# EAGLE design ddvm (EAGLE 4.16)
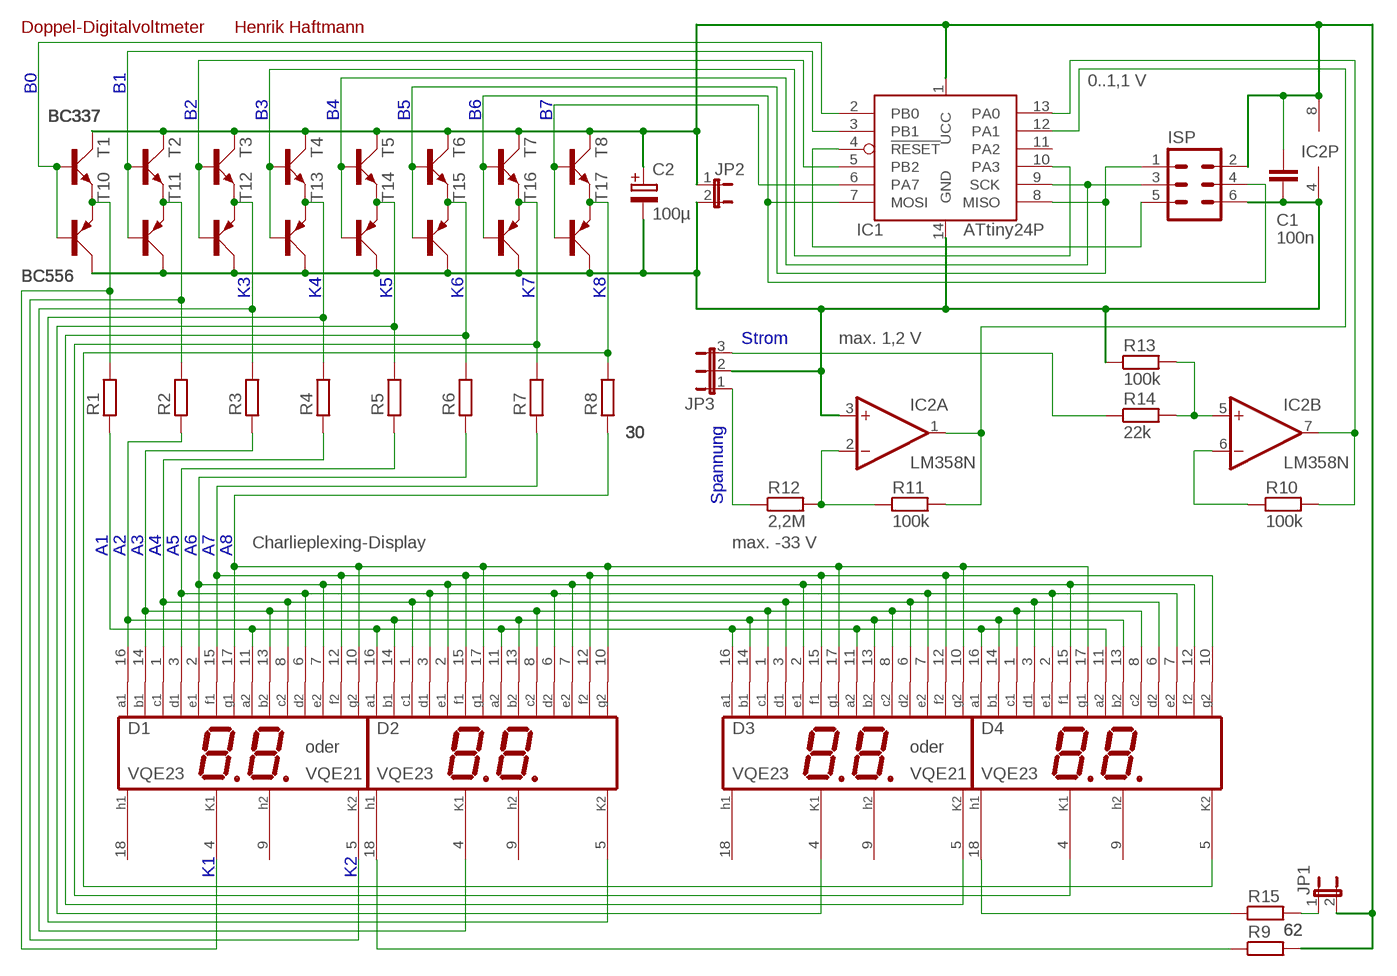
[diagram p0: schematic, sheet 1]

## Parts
C1  100n  C1  [C050-050X075]
C2  100µ  E1-2  [E1-2]
D1  VQE23  [VQE]
D2  VQE23  [VQE]
D3  VQE23  [VQE]
D4  VQE23  [VQE]
IC1  ATtiny24P  ATTINY24P  [DIL14]
IC2  LM358N  [DIL08]
ISP  MA03-2  [MA03-2]
JP1  JP1E  [JP1]
JP2  JP1E  [JP1]
JP3  JP2E  [JP2]
R1  30  R  [0207/2V]
R2  30  R  [0207/2V]
R3  30  R  [0207/2V]
R4  30  R  [0207/2V]
R5  30  R  [0207/2V]
R6  30  R  [0207/2V]
R7  30  R  [0207/2V]
R8  30  R  [0207/2V]
R9  62  R  [0207/2V]
R10  100k  R  [0207/2V]
R11  100k  R  [0207/2V]
R12  2,2M  R  [0207/2V]
R13  100k  R  [0207/2V]
R14  22k  R  [0207/2V]
R15  62  R  [0207/2V]
T1  BC337  NPN  [SOT54A]
T2  BC337  NPN  [SOT54A]
T3  BC337  NPN  [SOT54A]
T4  BC337  NPN  [SOT54A]
T5  BC337  NPN  [SOT54A]
T6  BC337  NPN  [SOT54A]
T7  BC337  NPN  [SOT54A]
T8  BC337  NPN  [SOT54A]
T10  BC556  PNP  [SOT54A]
T11  BC556  PNP  [SOT54A]
T12  BC556  PNP  [SOT54A]
T13  BC556  PNP  [SOT54A]
T14  BC556  PNP  [SOT54A]
T15  BC556  PNP  [SOT54A]
T16  BC556  PNP  [SOT54A]
T17  BC556  PNP  [SOT54A]

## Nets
5P: C1.1 C2.+ IC1.1(UCC) IC2.8(P:V+) ISP.2 JP1.2 JP2.1 R9.2 T1.C T2.C T3.C T4.C T5.C T6.C T7.C T8.C
A1: D1.11(A2) D2.11(A2) D2.16(A1) D3.11(A2) D3.16(A1) D4.11(A2) D4.16(A1) R1.1
A2: D1.16(A1) D2.13(B2) D2.14(B1) D3.13(B2) D3.14(B1) D4.13(B2) D4.14(B1) R2.1
A3: D1.13(B2) D1.14(B1) D2.8(C2) D3.1(C1) D3.8(C2) D4.1(C1) D4.8(C2) R3.1
A4: D1.1(C1) D1.8(C2) D2.1(C1) D3.3(D1) D3.6(D2) D4.3(D1) D4.6(D2) R4.1
A5: D1.3(D1) D1.6(D2) D2.3(D1) D2.6(D2) D3.7(E2) D4.2(E1) D4.7(E2) R5.1
A6: D1.2(E1) D1.7(E2) D2.2(E1) D2.7(E2) D3.2(E1) D4.12(F2) D4.15(F1) R6.1
A7: D1.12(F2) D1.15(F1) D2.12(F2) D2.15(F1) D3.12(F2) D3.15(F1) D4.10(G2) R7.1
A8: D1.10(G2) D1.17(G1) D2.10(G2) D2.17(G1) D3.10(G2) D3.17(G1) D4.17(G1) R8.1
B0: IC1.2(PB0) T1.B T10.B
B1: IC1.3(PB1) T2.B T11.B
B2: IC1.5(PB2) T3.B T12.B
B3: IC1.10(PA3) T4.B T13.B
B4: IC1.9(SCK) ISP.3 T5.B T14.B
B5: IC1.8(MISO) ISP.1 T6.B T15.B
B6: IC1.7(MOSI) ISP.4 T7.B T16.B
B7: IC1.6(PA7) T8.B T17.B
GND: C1.2 C2.- IC1.14(GND) IC2.3(A:+IN) IC2.4(P:V-) ISP.6 JP2.2 JP3.2 R13.1 T10.C T11.C T12.C T13.C T14.C T15.C T16.C T17.C
K1: D1.4(GK1) R1.2 T1.E T10.E
K2: D1.5(GK2) R2.2 T2.E T11.E
K3: D2.4(GK1) R3.2 T3.E T12.E
K4: D2.5(GK2) R4.2 T4.E T13.E
K5: D3.4(GK1) R5.2 T5.E T14.E
K6: D3.5(GK2) R6.2 T6.E T15.E
K7: D4.4(GK1) R7.2 T7.E T16.E
K8: D4.5(GK2) R8.2 T8.E T17.E
N$9: D2.18(H1) R9.1
N$18: D4.18(H1) R15.1
N$27: JP1.1 R15.2
N$30: JP3.1 R12.1
N$31: IC1.4(!RESET) ISP.5
N$32: JP3.3 R14.1
N$34: IC1.13(PA0) IC2.7(B:OUT) R10.2
N$35: IC1.12(PA1) IC2.1(A:OUT) R11.2
N$36: IC2.2(A:-IN) R11.1 R12.2
N$37: IC2.5(B:+IN) R13.2 R14.2
N$38: IC2.6(B:-IN) R10.1
Unconnected: D1.9(H2) D1.18(H1) D2.9(H2) D3.9(H2) D3.18(H1) D4.9(H2) IC1.11(PA2)

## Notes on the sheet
- Doppel-Digitalvoltmeter | Henrik Haftmann
- 0..1,1 V
- Strom | max. 1,2 V
- Spannung
- Charlieplexing-Display | max. -33 V
- oder | oder
- VQE21 | VQE21

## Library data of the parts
C1 = UZD1:C: Kondensator
C2 = galep:E: Elektrolytkondensator, gepolt
D1-D4 = UZD1:VQE*: LED-Anzeige 2 7-Segment-Ziffern 8.8.
IC1 = UZD1:ATTINY*4: 8-bit-Mikrocontroller Typmax. TaktFlashRAMEEPROM ATtiny2420 MHz2 kByte128 Byte128 Byte ATtiny24V10 MHz ATtiny4420 MHz4 kByte256 Byte256 Byte ATtiny44V10 MHz ATtiny84V10 MHz8 kByte512 Byte512 Byte
IC2 = linear:LM358: OP AMP also LM158; LM258; LM2904 Source: http://cache.national.com/ds/LM/LM158.pdf
ISP = con-lstb:MA03-2: PIN HEADER
JP1 JP2 = jumper:JP1E: JUMPER
JP3 = jumper:JP2E: JUMPER
R1-R15 = UZD1:R: Widerstand
T1-T8 = UZD1:NPN: npn-Trabsistor
T10-T17 = UZD1:PNP: pnp-Transistor

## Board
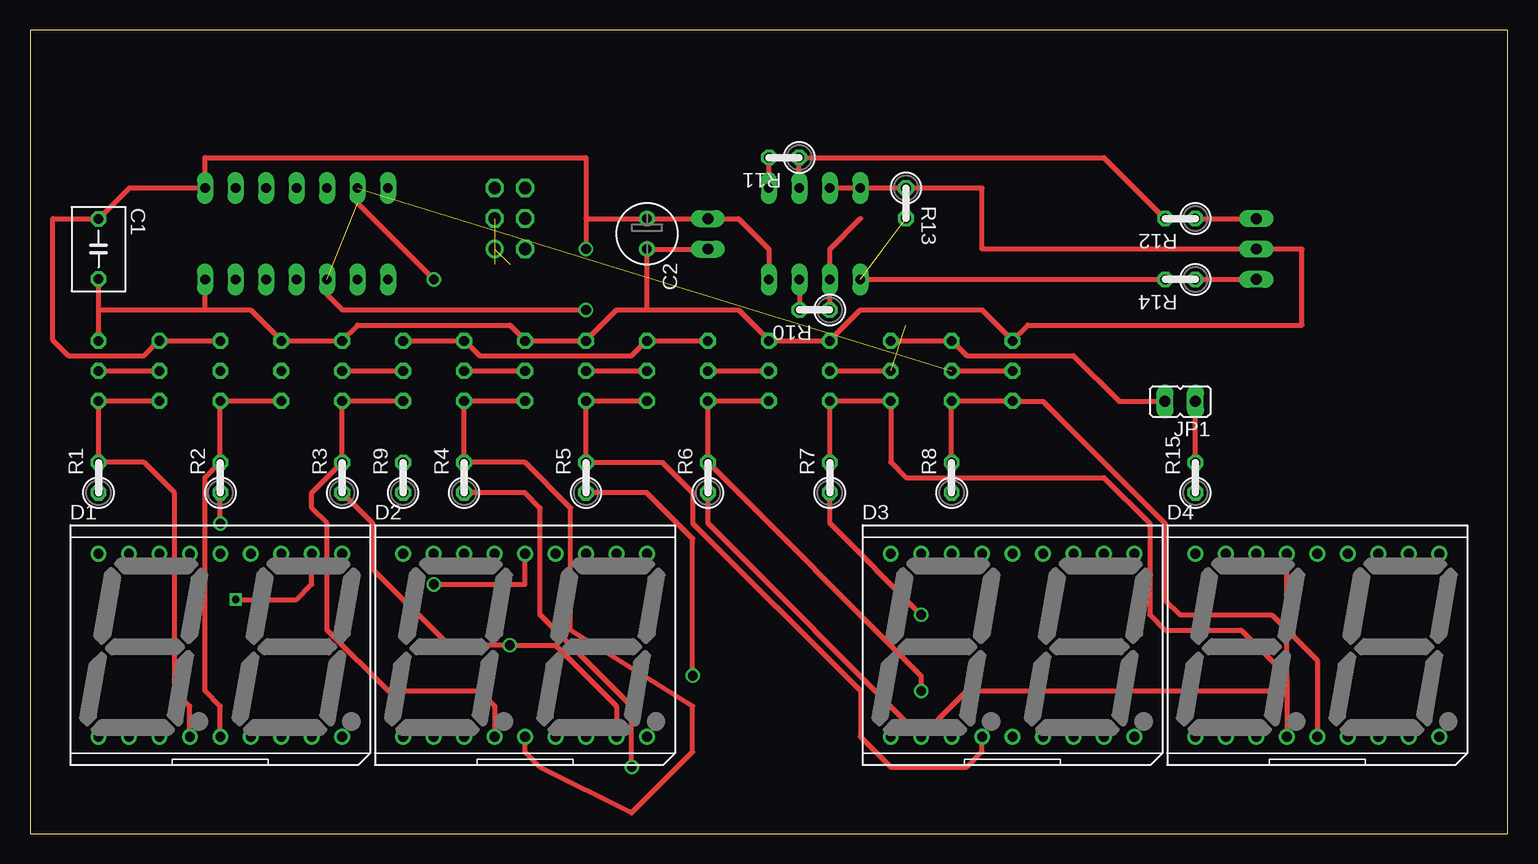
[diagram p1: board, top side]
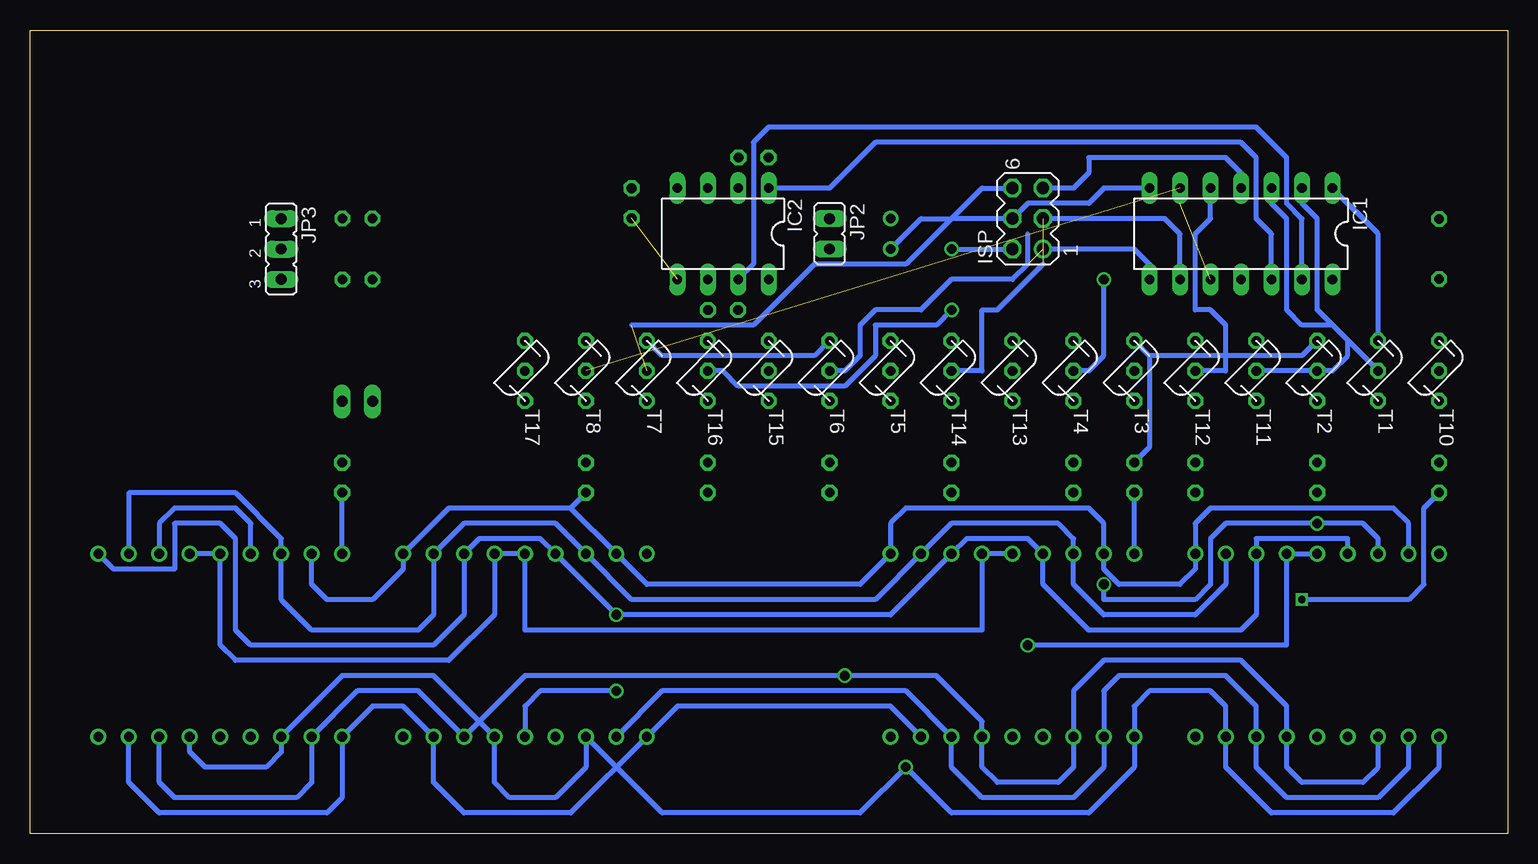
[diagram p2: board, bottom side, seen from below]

Size 123.17 x 66.98 mm. Coordinates in mm from the lower left corner, seen from the top.
Outline: 0,0 123.17,0 123.17,66.98 0,66.98 0,0
Copper layers (1*16): Top 0.035mm / dielectric 1.5mm / Bottom 0.035mm
Design rules "default": minimum track width 10mil, minimum drill 24mil, track to track 8mil, track to pad 8mil, pad to pad 8mil, via to via 8mil, smd to smd 8mil, copper to edge 40mil, drill to drill 8mil, minimum pad ring 10mil, minimum via ring 8mil, stop-mask expansion 4mil, vias tented up to drill 0mil, thermal gap 10mil

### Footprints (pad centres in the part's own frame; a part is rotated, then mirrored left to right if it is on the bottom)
C050-050X075 = drill 0.813 octagon: 1 -2.5,0; 2 2.5,0
E1-2 = drill 0.8 round: + -1.27,0; - 1.27,0
VQE = drill 0.813 round: 1 -10.16,-7.62; 2 -7.62,-7.62; 3 -5.08,-7.62; 4 -2.54,-7.62; 5 0,-7.62; 6 2.54,-7.62; 7 5.08,-7.62; 8 7.62,-7.62; 9 10.16,-7.62; 10 10.16,7.62; 11 7.62,7.62; 12 5.08,7.62; 13 2.54,7.62; 14 0,7.62; 15 -2.54,7.62; 16 -5.08,7.62; 17 -7.62,7.62; 18 -10.16,7.62
DIL14 = drill 0.813 long: 1 -7.62,-3.81; 2 -5.08,-3.81; 3 -2.54,-3.81; 4 0,-3.81; 5 2.54,-3.81; 6 5.08,-3.81; 7 7.62,-3.81; 8 7.62,3.81; 9 5.08,3.81; 10 2.54,3.81; 11 0,3.81; 12 -2.54,3.81; 13 -5.08,3.81; 14 -7.62,3.81
DIL08 = drill 0.813 long: 1 -3.81,-3.81; 2 -1.27,-3.81; 3 1.27,-3.81; 4 3.81,-3.81; 5 3.81,3.81; 6 1.27,3.81; 7 -1.27,3.81; 8 -3.81,3.81
MA03-2 = drill 1.016 round: 1 -2.54,-1.27 | drill 1.016 octagon: 2 -2.54,1.27; 3 0,-1.27; 4 0,1.27; 5 2.54,-1.27; 6 2.54,1.27
JP1 = drill 0.914 long: 1 0,-1.27; 2 0,1.27
JP2 = drill 0.914 long: 1 -2.54,0; 2 0,0; 3 2.54,0
0207/2V = drill 0.813 octagon: 1 -1.25,0; 2 1.25,0
SOT54A = drill 0.813 octagon: B 0,0; C -2.5,0; E 2.5,0

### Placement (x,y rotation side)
C1  5.71,48.73 270 top
C2  51.43,50 270 top
D1  15.87,15.71 0 top
D2  41.27,15.71 0 top
D3  81.91,15.71 0 top
D4  107.31,15.71 0 top
IC1  22.22,50 180 bottom
IC2  65.4,50 180 bottom
ISP  40,51.27 90 bottom
JP1  95.88,36.03 90 top
JP2  56.51,50 180 bottom
JP3  102.23,48.73 270 bottom
R1  5.71,29.68 90 top
R2  15.87,29.68 90 top
R3  26.03,29.68 90 top
R4  36.19,29.68 90 top
R5  46.35,29.68 90 top
R6  56.51,29.68 90 top
R7  66.67,29.68 90 top
R8  76.83,29.68 90 top
R9  31.11,29.68 90 top
R10  65.4,43.65 180 top
R11  62.86,56.35 180 top
R12  95.88,51.27 180 top
R13  73.02,52.54 270 top
R14  95.88,46.19 180 top
R15  97.15,29.68 90 top
T1  10.79,38.57 270 bottom
T2  15.87,38.57 270 bottom
T3  31.11,38.57 270 bottom
T4  36.19,38.57 270 bottom
T5  51.43,38.57 270 bottom
T6  56.51,38.57 270 bottom
T7  71.75,38.57 270 bottom
T8  76.83,38.57 270 bottom
T10  5.71,38.57 270 bottom
T11  20.95,38.57 270 bottom
T12  26.03,38.57 270 bottom
T13  41.27,38.57 270 bottom
T14  46.35,38.57 270 bottom
T15  61.59,38.57 270 bottom
T16  66.67,38.57 270 bottom
T17  81.91,38.57 270 bottom

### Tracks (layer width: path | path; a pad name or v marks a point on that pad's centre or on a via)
5P  (via drill 0.8)
  Top 0.406: 36.19,41.11 T4.C | T3.C 36.15,41.07 36.19,41.11 | v10.79,41.11 T1.C | T2.C 10.83,41.07 v10.79,41.11 | 51.43,41.11 T5.C | T6.C 51.47,41.07 51.43,41.11 | T7.C 76.79,41.07 76.83,41.11 T8.C 76.87,41.07 78.1,39.84 86.99,39.84 90.8,36.03 JP1.2 | 5.71,51.27 C1.1 | 5.71,51.27 8.25,53.81 IC1.1 14.6,56.35 46.35,56.35 46.35,51.27 | 36.19,41.11 37.46,39.84 50.16,39.84 51.43,41.11 | 46.35,51.27 v46.35,48.73 | 46.35,51.27 C2.+ JP2.1 59.05,51.27 61.59,48.73 IC2.8 | 5.71,51.27 1.9,51.27 1.9,41.11 3.17,39.84 9.52,39.84 v10.79,41.11
  Bottom 0.406: T2.C 15.91,41.07 17.14,39.84 29.84,39.84 | T3.C 31.11,41.11 29.84,39.84 | T5.C 51.43,41.11 | T6.C 56.55,41.07 57.78,39.84 70.48,39.84 71.75,41.11 T7.C | R9.2 31.11,30.95 29.84,32.22 29.84,39.84 | v10.79,41.11 10.79,50 IC1.1 | v46.35,48.73 ISP.2
A1  (via drill 0.6)
  Top 0.406: D1.11 23.49,20.79 22.22,19.52 v17.14,19.52
  Bottom 0.406: D4.11 114.93,28.41 106.04,28.41 102.23,24.6 D4.16 102.23,19.52 99.69,16.98 90.8,16.98 89.53,18.25 D3.11 86.99,25.87 79.37,25.87 D3.16 73.02,19.52 52.7,19.52 D2.11 46.35,25.87 37.46,25.87 36.19,24.6 D2.16 36.19,20.79 33.65,18.25 26.03,18.25 23.49,20.79 D1.11 | v17.14,19.52 8.25,19.52 6.98,20.79 6.98,27.14 5.71,28.41 R1.1
A2  (via drill 0.8)
  Top 0.406: v15.87,25.87 R2.1 | v33.65,20.79 41.27,20.79 D2.14
  Bottom 0.406: D4.13 D4.14 107.31,15.71 106.04,14.44 88.26,14.44 84.45,18.25 D3.13 D3.14 81.91,16.98 43.81,16.98 D2.13 D2.14 | D1.16 10.79,24.6 12.06,25.87 v15.87,25.87 23.49,25.87 24.76,24.6 24.76,20.79 26.03,19.52 33.65,19.52 v33.65,20.79
A3  (via drill 0.8)
  Top 0.406: D2.8 48.89,10.63 43.81,15.71 v40,15.71 34.92,15.71 28.57,22.06 28.57,25.87 26.03,28.41 R3.1
  Bottom 0.406: D1.14 D1.13 18.41,15.71 v40,15.71 | D2.8 51.43,10.63 69.21,10.63 D3.1 78.1,1.74 86.99,1.74 89.53,4.28 D3.8 92.07,10.63 94.61,10.63 D4.1 97.15,3.01 98.42,1.74 112.39,1.74 114.93,4.28 D4.8
A4  (via drill 0.8)
  Top 0.406: R4.1 41.25,28.43 42.54,27.14 42.54,18.25 50.16,10.63 v50.16,5.55
  Bottom 0.406: D1.1 5.71,5.55 9.52,1.74 19.68,1.74 23.49,5.55 D1.8 23.49,10.63 24.76,11.9 29.84,11.9 31.11,10.63 D2.1 31.11,5.55 34.92,1.74 46.35,1.74 v50.16,5.55 53.97,1.74 70.48,1.74 D3.3 76.83,5.55 79.37,3.01 83.18,3.01 84.45,4.28 D3.6 89.53,13.17 97.15,13.17 D4.3 102.23,6.82 103.5,5.55 108.58,5.55 109.85,6.82 D4.6
A5  (via drill 0.8)
  Top 0.406: R5.1 51.41,28.43 55.24,24.6 v55.24,13.17
  Bottom 0.406: D1.3 10.79,5.55 12.06,4.28 17.14,4.28 18.41,5.55 D1.6 18.41,10.63 22.22,14.44 33.65,14.44 36.19,11.9 D2.3 36.19,5.55 37.46,4.28 42.54,4.28 43.81,5.55 D2.6 43.81,9.36 47.62,13.17 v55.24,13.17 81.91,13.17 D3.7 90.8,11.9 95.88,11.9 D4.2 99.69,4.28 100.96,3.01 111.12,3.01 112.39,4.28 D4.7
A6
  Top 0.406: D4.15 104.77,11.9 78.1,11.9 D3.2 56.51,25.87 R6.1
  Bottom 0.406: D4.15 104.77,25.87 106.04,27.14 111.12,27.14 112.39,25.87 D4.12 | D3.2 70.48,11.9 50.16,11.9 D2.7 46.35,5.55 43.81,3.01 36.19,3.01 33.65,5.55 D2.2 33.65,11.9 32.38,13.17 23.49,13.17 20.95,10.63 D1.7 20.95,5.55 18.41,3.01 10.79,3.01 8.25,5.55 D1.2
A7  (via drill 0.8)
  Top 0.406: R7.1 66.67,25.87 v74.29,18.25
  Bottom 0.406: D4.10 116.2,22.06 111.12,22.06 111.12,25.87 107.31,25.87 106.04,24.6 106.04,16.98 104.77,15.71 89.53,15.71 86.99,18.25 D3.12 85.72,24.6 80.64,24.6 D3.15 v74.29,18.25 51.43,18.25 D2.12 45.08,24.6 40,24.6 D2.15 38.73,20.79 34.92,16.98 22.22,16.98 20.95,18.25 D1.12 20.95,24.6 13.33,24.6 D1.15
A8
  Bottom 0.406: 78.1,27.14 88.26,27.14 D3.10 92.07,22.06 94.61,19.52 98.42,19.52 99.69,20.79 D4.17 | 78.1,27.14 D3.17 71.75,20.79 53.97,20.79 D2.10 51.43,25.87 50.16,27.14 34.92,27.14 33.65,25.87 D2.17 33.65,22.06 32.38,20.79 27.3,20.79 26.03,22.06 D1.10 26.03,25.87 24.76,27.14 9.52,27.14 8.25,25.87 D1.17 | R8.1 76.83,28.41 78.1,27.14
B0
  Top 0.406: T10.B T1.B
  Bottom 0.406: IC1.2 17.14,52.54 15.87,51.27 15.87,43.65 T1.B
B1
  Bottom 0.406: IC1.3 19.68,52.54 18.41,51.27 18.41,43.65 17.14,42.38 14.6,42.38 13.33,41.11 13.33,39.84 14.6,38.57 T2.B T11.B
B2
  Top 0.406: T12.B T3.B
  Bottom 0.406: IC1.5 24.76,51.27 26.03,50 26.03,43.65 24.76,43.65 23.49,42.38 23.49,38.57 T12.B
B3  (via drill 0.8)  (1 unrouted)
  Top 0.406: T4.B T13.B | v33.65,46.19 27.3,52.54
  Bottom 0.406: v33.65,46.19 33.65,39.84 34.92,38.57 T4.B
B4  (1 unrouted)
  Top 0.406: T14.B T5.B
  Bottom 0.406: T14.B 43.81,38.57 43.81,43.65 42.54,43.65 38.73,47.46 | ISP.3 28.57,51.27 27.3,50 IC1.9
B5  (1 unrouted)
  Top 0.406: T6.B T15.B
  Bottom 0.406: T6.B 55.24,38.57 53.97,39.84 53.97,42.38 52.7,43.65 48.89,43.65 46.35,46.19 41.27,46.19 40,47.46 40,50 | IC1.8 29.84,47.46 31.11,48.73 ISP.1
B6  (via drill 0.8)  (1 unrouted)
  Top 0.406: T16.B T7.B | v46.35,43.65 26.03,43.65 24.76,44.92
  Bottom 0.406: T16.B 65.4,38.57 64.13,37.3 55.24,37.3 52.7,39.84 52.7,42.38 47.62,42.38 v46.35,43.65 | IC1.7 33.65,53.81 34.92,52.54 40,52.54 ISP.4 46.35,51.27 50.16,47.46 57.78,47.46 62.86,42.38 73.02,42.38
B7  (1 unrouted)
  Top 0.406: T8.B T17.B
GND
  Top 0.406: 46.35,41.11 T14.C | 46.35,41.11 46.31,41.07 T13.C 41.27,41.11 40,42.38 27.3,42.38 26.03,41.11 | 26.03,41.11 25.99,41.07 T11.C 20.95,41.11 18.41,43.65 14.6,43.65 | 66.67,41.11 T16.C | 66.67,41.11 66.63,41.07 T15.C 61.59,41.11 59.05,43.65 51.43,43.65 | T10.C 5.71,43.65 | 5.71,43.65 14.6,43.65 | 14.6,43.65 IC1.14 | 5.71,43.65 C1.2 | 26.03,41.11 T12.C | 46.35,41.11 48.89,43.65 51.43,43.65 | 51.43,43.65 C2.- JP2.2 | 66.67,41.11 69.21,43.65 79.37,43.65 81.91,41.11 | IC2.3 IC2.4 69.23,53.79 R13.1 79.35,53.79 79.37,53.81 79.37,48.73 JP3.2 106.04,48.73 106.04,42.38 83.18,42.38 81.91,41.11 | 81.91,41.11 T17.C
  Bottom 0.406: ISP.6 43.81,53.81 46.35,51.27 48.89,51.27 C2.-
K1
  Top 0.406: D1.4 13.33,10.63 12.06,11.9 12.06,28.41 9.52,30.95 5.71,30.95 | T1.E 10.79,36.03 10.75,36.07 T10.E 5.71,30.95 | 5.71,30.95 R1.2
K2
  Top 0.406: D1.5 15.87,10.63 14.6,11.9 14.6,29.68 15.87,30.95 | T11.E 20.95,36.03 20.91,36.07 T2.E 15.87,30.95 | 15.87,30.95 R2.2
K3
  Top 0.406: D2.4 38.73,10.63 37.46,11.9 29.84,11.9 24.76,16.98 24.76,25.87 23.49,27.14 23.49,28.41 26.03,30.95 | T3.E 31.11,36.03 31.07,36.07 T12.E 26.03,30.95 | 26.03,30.95 R3.2
K4
  Top 0.406: D2.5 41.27,6.82 42.54,5.55 50.16,1.74 55.24,6.82 55.24,10.63 45.08,16.98 45.08,27.14 41.27,30.95 36.19,30.95 R4.2 36.19,36.03 | T13.E 36.23,36.07 36.19,36.03 | 36.19,36.03 T4.E
K5
  Top 0.406: D3.4 79.37,6.82 78.1,5.55 71.75,5.55 69.21,8.09 69.21,11.9 55.24,25.87 55.24,28.41 52.7,30.95 46.35,30.95 | R5.2 46.35,30.95 | 46.35,30.95 T14.E 51.39,36.07 51.43,36.03 T5.E
K6  (via drill 0.8)
  Top 0.406: v74.29,11.9 74.29,13.17 56.51,30.95 | R6.2 56.51,30.95 | 56.51,30.95 56.51,36.03 | 56.51,36.03 T6.E | T15.E 56.55,36.07 56.51,36.03
  Bottom 0.406: D3.5 81.91,10.63 80.64,11.9 v74.29,11.9
K7
  Top 0.406: R7.2 T16.E 71.71,36.07 71.75,36.03 | 71.75,36.03 T7.E | 71.75,36.03 71.75,30.95 73.02,29.68 89.53,29.68 93.34,25.87 93.34,18.25 94.61,16.98 100.96,16.98 104.77,13.17 D4.4
K8
  Top 0.406: R8.2 T8.E 81.87,36.07 81.91,36.03 | 81.91,36.03 T17.E | 81.91,36.03 84.45,36.03 94.61,25.87 94.61,19.52 95.88,18.25 103.5,18.25 107.31,14.44 D4.5
N$9
  Bottom 0.406: D2.18 R9.1
N$18
  Bottom 0.406: D4.18 R15.1
N$27
  Top 0.406: R15.2 JP1.1
N$30
  Top 0.406: R12.1 JP3.1
N$31
  Bottom 0.406: IC1.4 22.22,55.08 23.49,56.35 34.92,56.35 34.92,55.08 36.19,53.81 ISP.5
N$32
  Top 0.406: R14.1 JP3.3
N$34
  Top 0.406: R10.2 64.15,46.17 IC2.7
  Bottom 0.406: IC1.13 17.14,51.27 18.41,52.54 18.41,56.35 20.95,58.89 61.59,58.89 62.86,57.62 62.86,47.46 IC2.7
N$35
  Top 0.406: R11.2 61.61,53.83 IC2.1
  Bottom 0.406: IC1.12 19.68,50 20.95,51.27 20.95,56.35 22.22,57.62 52.7,57.62 56.51,53.81 IC2.1
N$36
  Top 0.406: IC2.2 64.11,53.83 R11.1 89.53,56.35 94.61,51.27 R12.2
N$37  (1 unrouted)
  Top 0.406: IC2.5 R14.2
N$38
  Top 0.406: R10.1 66.67,43.65 IC2.6 66.67,48.73 69.23,51.29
